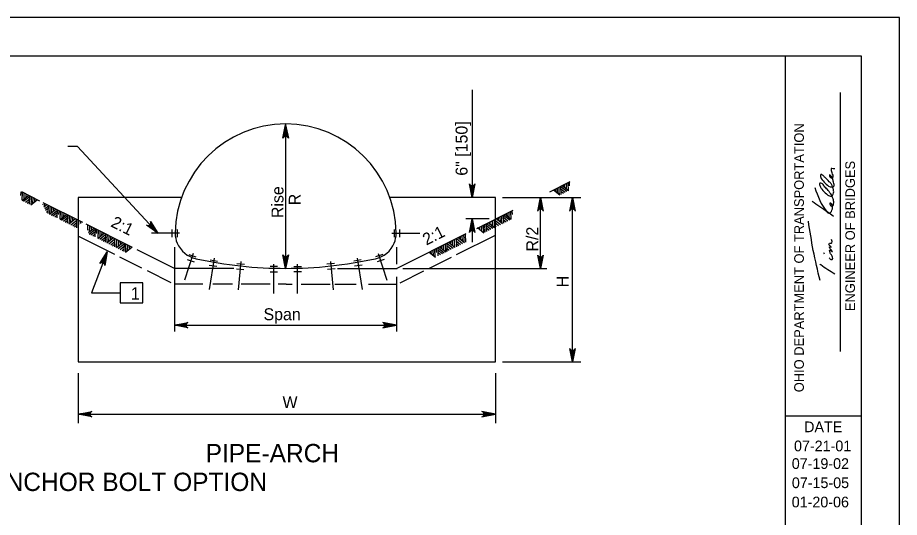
# Model space of a CAD drawing. Extents: x 1083.1 to 1117.1, y 675.4 to 741.4.
# Drawn here: x 1105.58 to 1117.13, y 734.81 to 741.35 of the extents above; entities that cross this region are included whole.
import ezdxf

# ---------------------------------------------------------------- set-up
doc = ezdxf.new("R2010")
doc.units = 0
doc.layers.add('Level 1', color=7, linetype='Continuous')

msp = doc.modelspace()

# ---------------------------------------------------------------- linework, layer by layer
at = {"layer": 'Level 1'}
for p, q in [((1115.636, 719.854), (1115.636, 740.854)), ((1111.533, 740.408), (1111.533, 739)), ((1116.355, 736.985), (1116.355, 740.375)), ((1109.067, 739.791), (1109.092, 739.953)), ((1109.078, 739.797), (1109.092, 739.953)), ((1109.092, 739.963), (1109.092, 738.623)), ((1109.092, 739.8), (1109.092, 739.953)), ((1109.104, 739.798), (1109.092, 739.953)), ((1109.115, 739.793), (1109.092, 739.953)), ((1111.511, 739.16), (1111.533, 739)), ((1111.522, 739.155), (1111.533, 739)), ((1111.558, 739.162), (1111.533, 739)), ((1111.548, 739.156), (1111.533, 739)), ((1111.533, 739.153), (1111.533, 739)), ((1112.551, 739.075), (1112.817, 739.208)), ((1112.652, 739.051), (1112.651, 739.123)), ((1112.673, 739.084), (1112.672, 739.133)), ((1112.697, 739.038), (1112.693, 739.144)), ((1112.774, 739.077), (1112.694, 739.141)), ((1112.796, 739.087), (1112.712, 739.154)), ((1112.744, 739.129), (1112.743, 739.169)), ((1112.769, 739.109), (1112.767, 739.181)), ((1112.793, 739.089), (1112.79, 739.193)), ((1112.81, 739.152), (1112.809, 739.202)), ((1105.626, 739.026), (1105.628, 739.076)), ((1105.872, 738.954), (1105.636, 739.072)), ((1105.641, 738.961), (1105.724, 739.028)), ((1105.643, 738.963), (1105.647, 739.067)), ((1105.662, 738.951), (1105.743, 739.015)), ((1105.668, 738.983), (1105.67, 739.055)), ((1105.693, 739.002), (1105.694, 739.043)), ((1105.74, 738.912), (1105.744, 739.018)), ((1105.763, 738.958), (1105.765, 739.007)), ((1112.68, 739.029), (1112.597, 739.096)), ((1112.629, 739.07), (1112.627, 739.111)), ((1112.675, 739.034), (1112.673, 739.084)), ((1112.751, 739.065), (1112.695, 739.11)), ((1112.728, 739.053), (1112.695, 739.08)), ((1105.686, 738.939), (1105.742, 738.984)), ((1105.709, 738.927), (1105.741, 738.954)), ((1105.757, 738.903), (1105.84, 738.97)), ((1105.762, 738.908), (1105.763, 738.958)), ((1105.784, 738.925), (1105.786, 738.997)), ((1105.808, 738.944), (1105.81, 738.985)), ((1105.911, 738.905), (1105.912, 738.91)), ((1106.436, 738.672), (1105.916, 738.932)), ((1105.927, 738.876), (1105.965, 738.907)), ((1105.934, 738.883), (1105.936, 738.922)), ((1105.938, 738.855), (1105.985, 738.892)), ((1105.983, 738.79), (1105.985, 738.897)), ((1106.377, 739), (1106.377, 736.847)), ((1107.72, 739), (1106.377, 739)), ((1111.839, 739), (1110.456, 739)), ((1111.839, 736.847), (1111.839, 739)), ((1111.929, 739), (1112.957, 739)), ((1112.404, 738.838), (1112.429, 739)), ((1112.414, 738.844), (1112.429, 739)), ((1112.429, 738.847), (1112.429, 739)), ((1112.44, 738.846), (1112.429, 739)), ((1112.451, 738.84), (1112.429, 739)), ((1112.429, 738.372), (1112.429, 738.997)), ((1112.448, 738.902), (1112.448, 738.907)), ((1112.822, 738.838), (1112.846, 739)), ((1112.832, 738.844), (1112.846, 739)), ((1112.846, 738.847), (1112.846, 739)), ((1112.858, 738.846), (1112.846, 739)), ((1112.869, 738.84), (1112.846, 739)), ((1112.846, 737.708), (1112.846, 739)), ((1105.95, 738.832), (1105.984, 738.86)), ((1105.963, 738.809), (1105.984, 738.826)), ((1106.001, 738.781), (1106.084, 738.848)), ((1106.004, 738.783), (1106.007, 738.887)), ((1106.022, 738.77), (1106.103, 738.835)), ((1106.028, 738.803), (1106.03, 738.875)), ((1106.046, 738.759), (1106.102, 738.804)), ((1106.053, 738.822), (1106.054, 738.863)), ((1106.1, 738.732), (1106.104, 738.838)), ((1106.123, 738.778), (1106.125, 738.827)), ((1106.138, 738.713), (1106.221, 738.779)), ((1106.141, 738.715), (1106.144, 738.818)), ((1106.165, 738.734), (1106.167, 738.806)), ((1106.19, 738.754), (1106.191, 738.794)), ((1111.593, 738.596), (1112.072, 738.836)), ((1112.046, 738.713), (1111.963, 738.779)), ((1111.995, 738.754), (1111.993, 738.794)), ((1112.02, 738.734), (1112.017, 738.806)), ((1112.044, 738.715), (1112.041, 738.818)), ((1112.061, 738.778), (1112.059, 738.827)), ((1106.069, 738.747), (1106.102, 738.774)), ((1106.159, 738.702), (1106.24, 738.766)), ((1106.183, 738.69), (1106.239, 738.736)), ((1106.206, 738.679), (1106.238, 738.705)), ((1106.237, 738.663), (1106.241, 738.77)), ((1106.254, 738.655), (1106.337, 738.721)), ((1106.259, 738.659), (1106.26, 738.709)), ((1106.26, 738.709), (1106.262, 738.759)), ((1106.28, 738.642), (1106.359, 738.705)), ((1106.281, 738.677), (1106.283, 738.748)), ((1106.304, 738.63), (1106.359, 738.673)), ((1106.305, 738.696), (1106.307, 738.736)), ((1106.356, 738.603), (1106.36, 738.71)), ((1106.383, 738.648), (1106.384, 738.698)), ((1106.409, 738.66), (1106.409, 738.685)), ((1106.432, 738.671), (1106.433, 738.674)), ((1107.326, 738.667), (1107.419, 738.532)), ((1111.756, 738.719), (1111.45, 738.719)), ((1111.509, 738.557), (1111.533, 738.719)), ((1111.519, 738.563), (1111.533, 738.719)), ((1111.533, 738.719), (1111.533, 738.414)), ((1111.533, 738.566), (1111.533, 738.719)), ((1111.545, 738.565), (1111.533, 738.719)), ((1111.556, 738.559), (1111.533, 738.719)), ((1111.726, 738.554), (1111.722, 738.66)), ((1111.828, 738.601), (1111.742, 738.67)), ((1111.769, 738.649), (1111.768, 738.682)), ((1111.802, 738.622), (1111.8, 738.698)), ((1111.828, 738.603), (1111.825, 738.71)), ((1111.905, 738.642), (1111.825, 738.705)), ((1111.88, 738.63), (1111.826, 738.673)), ((1111.931, 738.655), (1111.847, 738.721)), ((1111.879, 738.696), (1111.878, 738.736)), ((1111.903, 738.677), (1111.901, 738.748)), ((1111.924, 738.709), (1111.922, 738.759)), ((1111.925, 738.659), (1111.924, 738.709)), ((1111.947, 738.663), (1111.944, 738.77)), ((1112.025, 738.702), (1111.945, 738.766)), ((1112.001, 738.69), (1111.945, 738.736)), ((1111.979, 738.679), (1111.946, 738.705)), ((1106.329, 738.617), (1106.358, 738.64)), ((1107.088, 738.346), (1106.482, 738.649)), ((1106.483, 738.646), (1106.483, 738.649)), ((1106.502, 738.574), (1106.504, 738.638)), ((1106.51, 738.543), (1106.582, 738.599)), ((1106.52, 738.522), (1106.6, 738.586)), ((1106.525, 738.554), (1106.527, 738.626)), ((1106.543, 738.51), (1106.6, 738.555)), ((1106.55, 738.574), (1106.551, 738.614)), ((1106.597, 738.483), (1106.601, 738.589)), ((1106.621, 738.529), (1106.622, 738.579)), ((1106.638, 738.466), (1106.641, 738.569)), ((1106.662, 738.485), (1106.664, 738.558)), ((1106.687, 738.505), (1106.688, 738.546)), ((1107.293, 738.633), (1107.419, 738.532)), ((1107.305, 738.637), (1107.419, 738.532)), ((1107.315, 738.643), (1107.419, 738.532)), ((1107.323, 738.655), (1107.419, 738.532)), ((1107.602, 738.581), (1107.602, 738.482)), ((1107.672, 738.582), (1107.672, 738.482)), ((1109.092, 738.623), (1109.092, 738.072)), ((1110.513, 738.582), (1110.513, 738.482)), ((1110.582, 738.581), (1110.582, 738.482)), ((1111.688, 738.535), (1111.605, 738.602)), ((1111.636, 738.576), (1111.635, 738.617)), ((1111.661, 738.556), (1111.659, 738.629)), ((1111.685, 738.537), (1111.682, 738.64)), ((1111.704, 738.544), (1111.701, 738.65)), ((1111.803, 738.593), (1111.723, 738.657)), ((1111.78, 738.581), (1111.724, 738.626)), ((1111.757, 738.57), (1111.724, 738.596)), ((1111.848, 738.614), (1111.827, 738.631)), ((1106.855, 738.254), (1106.377, 738.493)), ((1106.566, 738.499), (1106.599, 738.525)), ((1106.635, 738.464), (1106.718, 738.531)), ((1106.657, 738.453), (1106.737, 738.518)), ((1106.68, 738.442), (1106.736, 738.487)), ((1106.703, 738.43), (1106.736, 738.457)), ((1106.734, 738.414), (1106.738, 738.521)), ((1106.751, 738.406), (1106.834, 738.473)), ((1106.756, 738.41), (1106.757, 738.461)), ((1106.757, 738.461), (1106.759, 738.51)), ((1106.777, 738.393), (1106.856, 738.457)), ((1106.778, 738.428), (1106.78, 738.5)), ((1106.803, 738.447), (1106.804, 738.488)), ((1106.854, 738.355), (1106.857, 738.462)), ((1106.879, 738.346), (1106.882, 738.449)), ((1106.904, 738.366), (1106.907, 738.437)), ((1107.703, 738.532), (1107.336, 738.532)), ((1110.481, 738.532), (1110.848, 738.532)), ((1110.545, 738.072), (1111.455, 738.527)), ((1111.28, 738.366), (1111.278, 738.437)), ((1111.306, 738.346), (1111.303, 738.449)), ((1111.331, 738.355), (1111.328, 738.462)), ((1111.408, 738.393), (1111.328, 738.457)), ((1111.33, 738.254), (1111.839, 738.509)), ((1111.433, 738.406), (1111.35, 738.473)), ((1111.382, 738.447), (1111.38, 738.488)), ((1111.406, 738.428), (1111.404, 738.5)), ((1111.427, 738.461), (1111.425, 738.51)), ((1111.428, 738.41), (1111.427, 738.461)), ((1111.45, 738.414), (1111.447, 738.521)), ((1106.802, 738.381), (1106.856, 738.424)), ((1106.826, 738.369), (1106.855, 738.392)), ((1106.876, 738.344), (1106.959, 738.41)), ((1106.9, 738.332), (1106.979, 738.395)), ((1106.925, 738.319), (1106.979, 738.363)), ((1106.928, 738.386), (1106.93, 738.425)), ((1106.95, 738.307), (1106.978, 738.329)), ((1106.977, 738.293), (1106.98, 738.4)), ((1106.995, 738.284), (1107.079, 738.351)), ((1106.998, 738.286), (1107.001, 738.389)), ((1107.022, 738.305), (1107.024, 738.378)), ((1107.047, 738.325), (1107.048, 738.366)), ((1107.635, 738.072), (1107.148, 738.316)), ((1107.635, 738.351), (1107.635, 737.245)), ((1110.541, 738.351), (1110.541, 738.129)), ((1111.05, 738.218), (1111.047, 738.321)), ((1111.067, 738.281), (1111.065, 738.33)), ((1111.09, 738.235), (1111.087, 738.341)), ((1111.168, 738.273), (1111.087, 738.338)), ((1111.189, 738.284), (1111.106, 738.351)), ((1111.137, 738.325), (1111.136, 738.366)), ((1111.162, 738.305), (1111.16, 738.378)), ((1111.187, 738.286), (1111.184, 738.389)), ((1111.208, 738.293), (1111.205, 738.4)), ((1111.284, 738.332), (1111.205, 738.395)), ((1111.26, 738.319), (1111.206, 738.363)), ((1111.234, 738.307), (1111.207, 738.329)), ((1111.308, 738.344), (1111.225, 738.41)), ((1111.256, 738.386), (1111.255, 738.425)), ((1111.383, 738.381), (1111.329, 738.424)), ((1111.358, 738.369), (1111.33, 738.392)), ((1112.429, 738.069), (1112.429, 738.372)), ((1106.757, 738.287), (1106.551, 737.752)), ((1106.675, 738.144), (1106.757, 738.287)), ((1106.687, 738.146), (1106.757, 738.287)), ((1106.701, 738.144), (1106.757, 738.287)), ((1106.711, 738.138), (1106.757, 738.287)), ((1106.72, 738.129), (1106.757, 738.287)), ((1107.211, 738.076), (1106.921, 738.221)), ((1107.88, 738.268), (1107.766, 737.92)), ((1107.823, 738.254), (1107.918, 738.223)), ((1108.157, 738.207), (1108.091, 737.795)), ((1109.07, 738.233), (1109.092, 738.072)), ((1109.081, 738.227), (1109.092, 738.072)), ((1109.117, 738.235), (1109.092, 738.072)), ((1109.107, 738.228), (1109.092, 738.072)), ((1109.092, 738.226), (1109.092, 738.072)), ((1110.028, 738.207), (1110.093, 737.795)), ((1110.362, 738.254), (1110.267, 738.223)), ((1110.304, 738.268), (1110.418, 737.92)), ((1111.052, 738.216), (1110.969, 738.282)), ((1110.974, 738.076), (1111.263, 738.221)), ((1111, 738.257), (1110.999, 738.297)), ((1111.026, 738.237), (1111.023, 738.309)), ((1111.144, 738.262), (1111.088, 738.307)), ((1111.121, 738.25), (1111.089, 738.276)), ((1112.407, 738.23), (1112.429, 738.069)), ((1112.418, 738.224), (1112.429, 738.069)), ((1112.454, 738.232), (1112.429, 738.069)), ((1112.444, 738.226), (1112.429, 738.069)), ((1112.429, 738.223), (1112.429, 738.069)), ((1116.145, 738.257), (1116.136, 738.276)), ((1107.802, 738.188), (1107.896, 738.157)), ((1108.092, 738.115), (1108.19, 738.099)), ((1108.102, 738.183), (1108.201, 738.168)), ((1108.453, 738.135), (1108.553, 738.126)), ((1108.506, 738.162), (1108.471, 737.79)), ((1108.987, 738.097), (1108.887, 738.097)), ((1108.937, 737.744), (1108.937, 738.129)), ((1109.198, 738.097), (1109.298, 738.097)), ((1109.248, 737.744), (1109.248, 738.129)), ((1109.731, 738.135), (1109.632, 738.126)), ((1109.679, 738.162), (1109.714, 737.79)), ((1110.082, 738.183), (1109.984, 738.168)), ((1110.093, 738.115), (1109.994, 738.099)), ((1110.383, 738.188), (1110.288, 738.157)), ((1107.593, 737.885), (1107.285, 738.039)), ((1108.415, 738.072), (1107.635, 738.072)), ((1108.447, 738.066), (1108.546, 738.057)), ((1108.887, 738.028), (1108.987, 738.028)), ((1109.298, 738.028), (1109.198, 738.028)), ((1109.738, 738.066), (1109.638, 738.057)), ((1109.769, 738.072), (1110.55, 738.072)), ((1110.302, 738.072), (1110.458, 738.072)), ((1110.591, 737.885), (1110.899, 738.039)), ((1110.628, 738.072), (1112.513, 738.072)), ((1106.925, 737.883), (1106.925, 737.621)), ((1107.224, 737.883), (1106.925, 737.883)), ((1107.224, 737.621), (1107.224, 737.883)), ((1108.007, 737.864), (1107.635, 737.864)), ((1108.395, 737.864), (1108.139, 737.864)), ((1108.888, 737.864), (1108.509, 737.864)), ((1109.099, 737.864), (1108.994, 737.864)), ((1109.099, 737.864), (1109.179, 737.864)), ((1109.296, 737.864), (1109.675, 737.864)), ((1109.735, 737.864), (1110.016, 737.864)), ((1110.178, 737.864), (1110.541, 737.864)), ((1110.541, 737.963), (1110.541, 737.245)), ((1106.551, 737.752), (1106.925, 737.752)), ((1112.846, 736.847), (1112.846, 737.708)), ((1106.925, 737.621), (1107.224, 737.621)), ((1107.795, 737.351), (1107.635, 737.328)), ((1107.79, 737.34), (1107.635, 737.328)), ((1107.635, 737.328), (1109.431, 737.328)), ((1107.788, 737.328), (1107.635, 737.328)), ((1107.791, 737.314), (1107.635, 737.328)), ((1107.797, 737.303), (1107.635, 737.328)), ((1109.431, 737.328), (1110.541, 737.328)), ((1110.379, 737.303), (1110.541, 737.328)), ((1110.381, 737.351), (1110.541, 737.328)), ((1110.385, 737.314), (1110.541, 737.328)), ((1110.386, 737.34), (1110.541, 737.328)), ((1110.388, 737.328), (1110.541, 737.328)), ((1112.824, 737.008), (1112.846, 736.847)), ((1112.835, 737.002), (1112.846, 736.847)), ((1112.871, 737.01), (1112.846, 736.847)), ((1112.861, 737.004), (1112.846, 736.847)), ((1112.846, 737.001), (1112.846, 736.847)), ((1106.377, 736.847), (1111.839, 736.847)), ((1111.929, 736.847), (1112.957, 736.847)), ((1106.377, 736.7), (1106.377, 736.044)), ((1111.839, 736.7), (1111.839, 736.044)), ((1106.537, 736.187), (1106.377, 736.164)), ((1106.532, 736.175), (1106.377, 736.164)), ((1106.53, 736.164), (1106.377, 736.164)), ((1106.533, 736.15), (1106.377, 736.164)), ((1106.539, 736.139), (1106.377, 736.164)), ((1106.377, 736.164), (1109.268, 736.164)), ((1109.268, 736.164), (1111.839, 736.164)), ((1111.677, 736.139), (1111.839, 736.164)), ((1111.679, 736.187), (1111.839, 736.164)), ((1111.683, 736.15), (1111.839, 736.164)), ((1111.684, 736.175), (1111.839, 736.164)), ((1111.686, 736.164), (1111.839, 736.164)), ((1116.626, 736.138), (1115.636, 736.138))]:
    msp.add_line(p, q, dxfattribs=at)
for points in [[(1083.126, 719.354), (1117.126, 719.354), (1117.126, 741.354), (1083.126, 741.354)], [(1085.126, 740.854), (1116.626, 740.854), (1116.626, 719.854), (1085.126, 719.854)]]:
    msp.add_lwpolyline(points, close=True, dxfattribs=at)
for points in [[(1109.057, 739.776), (1109.092, 739.953), (1109.128, 739.776)], [(1107.419, 738.532), (1106.367, 739.668), (1106.239, 739.668)], [(1111.569, 739.177), (1111.533, 739), (1111.498, 739.177)], [(1112.393, 738.823), (1112.429, 739), (1112.464, 738.823)], [(1112.811, 738.823), (1112.846, 739), (1112.882, 738.823)], [(1107.324, 738.685), (1107.419, 738.532), (1107.272, 738.636)], [(1111.498, 738.542), (1111.533, 738.719), (1111.569, 738.542)], [(1106.66, 738.134), (1106.757, 738.287), (1106.726, 738.109)], [(1109.128, 738.25), (1109.092, 738.072), (1109.057, 738.25)], [(1112.465, 738.246), (1112.429, 738.069), (1112.394, 738.246)], [(1107.812, 737.293), (1107.635, 737.328), (1107.812, 737.364)], [(1110.364, 737.293), (1110.541, 737.328), (1110.364, 737.364)], [(1112.882, 737.024), (1112.846, 736.847), (1112.811, 737.024)], [(1106.554, 736.129), (1106.377, 736.164), (1106.554, 736.2)], [(1111.662, 736.129), (1111.839, 736.164), (1111.662, 736.2)]]:
    msp.add_lwpolyline(points, dxfattribs=at)
for centre, start, end in [((1109.092, 739.762), 22.0878, 157.9139), ((1111.533, 739.192), 202.0878, 337.9139), ((1112.429, 738.809), 22.0878, 157.9139), ((1112.846, 738.809), 22.0878, 157.9139), ((1107.288, 738.671), 245.3126, 21.1387), ((1111.533, 738.528), 22.0878, 157.9139), ((1109.092, 738.264), 202.0878, 337.9139), ((1112.429, 738.261), 202.0878, 337.9139), ((1106.688, 738.108), 0.8903, 136.7164), ((1107.826, 737.328), 112.0878, 247.9139), ((1110.35, 737.328), 292.0861, 67.9122), ((1112.846, 737.039), 202.0878, 337.9139), ((1106.568, 736.164), 112.0878, 247.9139), ((1111.648, 736.164), 292.0861, 67.9122)]:
    msp.add_arc(centre, 0.0382, start, end, dxfattribs=at)
for centre, major_axis, start_param, end_param in [((1109.097, 738.51), (-1.453, 0), 4.71537, 6.266539), ((1109.088, 738.51), (1.453, 0), 0.016646, 1.567816), ((1108.091, 738.558), (-0.448, 0), 0.055055, 0.354919), ((1110.093, 738.558), (0.448, 0), 5.928267, 6.22813), ((1107.993, 738.541), (-0.35, 0), 0.40505, 1.357703), ((1110.192, 738.541), (0.35, 0), 4.925482, 5.878135), ((1109.081, 743.491), (5.419, 0), 4.496144, 4.714418), ((1109.103, 743.491), (-5.419, 0), 1.568767, 1.787041)]:
    msp.add_ellipse(centre, major_axis=major_axis, ratio=0.999895, start_param=start_param, end_param=end_param, dxfattribs=at)
for points in [[(1116.019, 739.132), (1116.184, 738.804), (1116.198, 738.793), (1116.207, 738.793), (1116.236, 738.817), (1116.249, 738.851), (1116.245, 738.902), (1116.23, 738.924), (1116.217, 738.924), (1116.216, 738.911), (1116.225, 738.896), (1116.237, 738.888), (1116.251, 738.888), (1116.264, 738.909), (1116.267, 738.929), (1116.258, 738.984), (1116.184, 739.104), (1116.143, 739.149), (1116.11, 739.184), (1116.087, 739.186), (1116.089, 739.147), (1116.112, 739.108), (1116.172, 739.046), (1116.21, 739.021), (1116.24, 739.016), (1116.261, 739.042), (1116.267, 739.076), (1116.263, 739.102), (1116.236, 739.175), (1116.209, 739.207), (1116.154, 739.261), (1116.128, 739.287), (1116.098, 739.302), (1116.095, 739.274), (1116.104, 739.248), (1116.156, 739.188), (1116.219, 739.141), (1116.266, 739.143), (1116.264, 739.201), (1116.254, 739.244), (1116.242, 739.269), (1116.233, 739.28), (1116.212, 739.295), (1116.213, 739.278), (1116.245, 739.257), (1116.258, 739.267), (1116.246, 739.321), (1116.239, 739.349), (1116.236, 739.362), (1116.236, 739.374), (1116.236, 739.383), (1116.258, 739.381), (1116.281, 739.381)], [(1115.984, 738.95), (1116.186, 738.813), (1116.263, 738.757)], [(1116.089, 737.913), (1116, 738.308), (1115.936, 738.691)], [(1116.207, 738.212), (1116.214, 738.201), (1116.248, 738.188), (1116.252, 738.221), (1116.23, 738.257), (1116.216, 738.293), (1116.216, 738.313), (1116.23, 738.306), (1116.239, 738.296), (1116.248, 738.291), (1116.227, 738.323), (1116.216, 738.338), (1116.213, 738.356), (1116.234, 738.349), (1116.227, 738.358), (1116.204, 738.386), (1116.213, 738.401), (1116.228, 738.403), (1116.236, 738.401), (1116.245, 738.422), (1116.239, 738.45)], [(1116.283, 737.997), (1116.098, 738.117), (1116.084, 738.128)]]:
    msp.add_spline(points, degree=3, dxfattribs=at)

# ---------------------------------------------------------------- texts
for s, height, rotation, p in [('6" [150]', 0.156, 90, (1111.473, 739.285)), ('OHIO DEPARTMENT OF TRANSPORTATION', 0.126, 90, (1115.876, 736.451)), ('ENGINEER OF BRIDGES', 0.126, 90, (1116.545, 737.513)), ('Rise', 0.156, 90, (1109.063, 738.73)), ('R', 0.156, 90, (1109.289, 738.898)), ('2:1', 0.156, 333.4374, (1106.791, 738.625)), ('2:1', 0.156, 26.5626, (1110.933, 738.369)), ('R/2', 0.156, 90, (1112.398, 738.293)), ('H', 0.156, 90, (1112.797, 737.824)), ('DATE', 0.14, 360, (1115.88, 735.928))]:
    msp.add_text(s, height=height, rotation=rotation, dxfattribs=at).set_placement(p)
for s, height, p in [('1', 0.16, (1107.064, 737.664)), ('Span', 0.156, (1108.802, 737.394)), ('W', 0.156, (1109.051, 736.243)), ('PIPE-ARCH', 0.24, (1108.044, 735.534)), ('07-21-01', 0.14, (1115.747, 735.678)), ('07-19-02', 0.14, (1115.718, 735.447)), ('METAL PIPE END TREATMENT "A" W/ANCHOR BOLT OPTION', 0.24, (1099.491, 735.158)), ('07-15-05', 0.14, (1115.719, 735.196)), ('01-20-06', 0.14, (1115.717, 734.944))]:
    msp.add_text(s, height=height, dxfattribs=at).set_placement(p)

doc.saveas('drawing.dxf')
